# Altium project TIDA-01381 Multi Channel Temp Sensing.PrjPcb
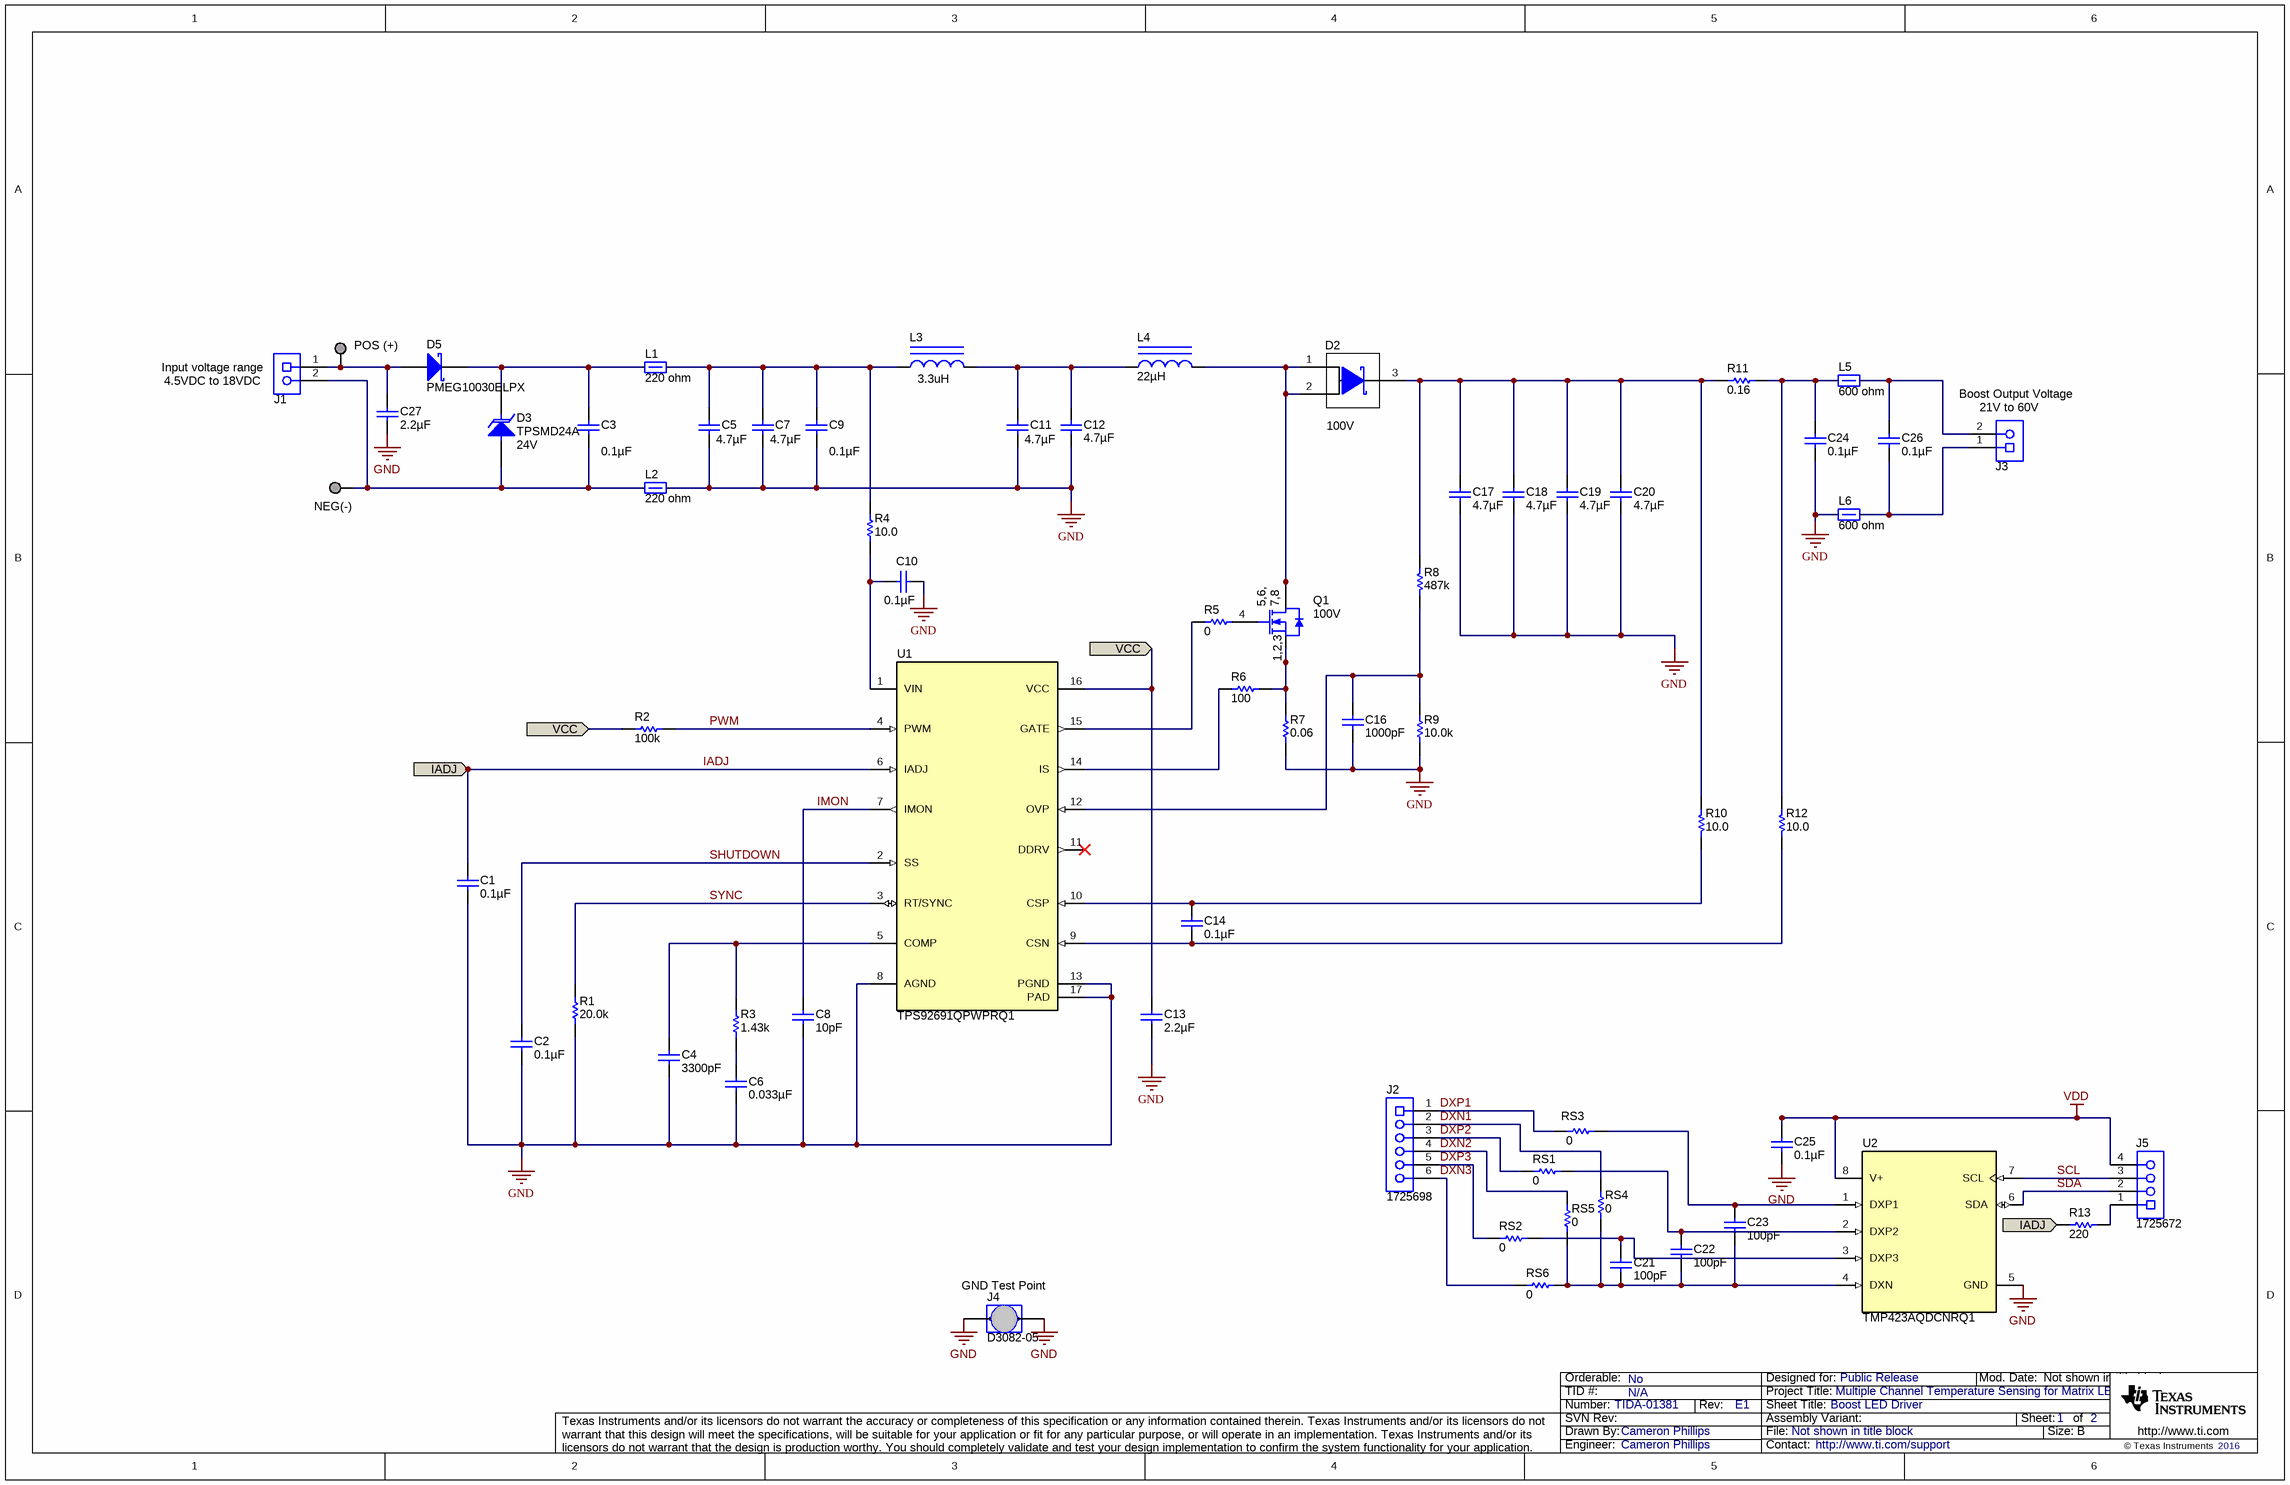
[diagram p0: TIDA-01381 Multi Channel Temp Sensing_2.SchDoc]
CopyrightYear: 2016; EVM_Orderable: No; PCB_Layout: Cameron Phillips; PCB_Rev: E1; PRJ_Customer: Public Release; PRJ_Engineer: Cameron Phillips; PRJ_Number: TIDA-01381; PRJ_Title: Multiple Channel Temperature Sensing for Matrix LED Headlight; SCH_Rev: E1; TechSupport: http://www.ti.com/support; TID: N/A
2 sheets, 84 parts. Net scope: flat (ports and power ports of the same name join across sheets).
Board file: TIDA-01381 Multi Channel Temp Sensing.PcbDoc
Sheets:
  TIDA-01381 Multi Channel Temp Sensing_2.SchDoc
  TIDA-01381 Multi Channel Temp Sensing_Hardware.SchDoc

## Sheet TIDA-01381 Multi Channel Temp Sensing_2.SchDoc: Boost LED Driver
size 431 x 279 mm; Date: Not shown in title block; ApprovedBy: Not shown in title block; CheckedBy: Not shown in title block; Author: Not shown in title block; CompanyName: Not shown in title block; DrawnBy: Cameron Phillips; Engineer: Not shown in title block; Organization: Not shown in title block; Address1: Not shown in title block; Address2: Not shown in title block; Address3: Not shown in title block; Address4: Not shown in title block; DocumentNumber: 1; Revision: Use project parameter SCH_Rev; SheetNumber: 1; SheetTotal: 2; PageSetup: Record=PageOptions¦CenterHorizontal=True¦CenterVertical=True¦PrintScale=0.61¦XCorrection=1.00¦YCorrection=1.00¦PrintKind=0¦BorderSize=5000000¦LeftOffset=0¦BottomOffset=0¦Orientation=2¦PaperLength=1000¦PaperWidth=1000¦Scale=100¦PaperSource=15¦PrintQuality=600¦MediaType=1¦DitherType=10¦PrintScaleMode=1¦PaperKind=Letter

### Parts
C1  ValueDisplayed: 0.1µF  [0603S]  (hidden comment: 06033C104JAT2A)
C2  ValueDisplayed: 0.1µF  [0603S]  (hidden comment: 06033C104JAT2A)
C3  ValueDisplayed: 0.1µF  [0805_HV]  (hidden comment: C2012X7R2A104K125AA)
C4  ValueDisplayed: 3300pF  [0603S]  (hidden comment: GRM188R71E332KA01D)
C5  ValueDisplayed: 4.7µF  [1210]  (hidden comment: C3225X7S2A475K200AE)
C6  ValueDisplayed: 0.033µF  [0805_HV]  (hidden comment: GRM216R71E333KA01D)
C7  ValueDisplayed: 4.7µF  [1210]  (hidden comment: C3225X7S2A475K200AE)
C8  ValueDisplayed: 10pF  [0603S]  (hidden comment: CGA3E2C0G1H100D080AA)
C9  ValueDisplayed: 0.1µF  [0805_HV]  (hidden comment: C2012X7R2A104K125AA)
C10  ValueDisplayed: 0.1µF  [0805_HV]  (hidden comment: C2012X7R2A104K125AA)
C11  ValueDisplayed: 4.7µF  [1210]  (hidden comment: C3225X7S2A475K200AE)
C12  ValueDisplayed: 4.7µF  [1210]  (hidden comment: C3225X7S2A475K200AE)
C13  ValueDisplayed: 2.2µF  [0805_HV]  (hidden comment: C0805C225K4RACTU)
C14  ValueDisplayed: 0.1µF  [0603S]  (hidden comment: GRM188R71H104KA93D)
C16  ValueDisplayed: 1000pF  [0603_HV]  (hidden comment: 06031C102JAT2A)
C17  ValueDisplayed: 4.7µF  [1210]  (hidden comment: C3225X7S2A475K200AE)
C18  ValueDisplayed: 4.7µF  [1210]  (hidden comment: C3225X7S2A475K200AE)
C19  ValueDisplayed: 4.7µF  [1210]  (hidden comment: C3225X7S2A475K200AE)
C20  ValueDisplayed: 4.7µF  [1210]  (hidden comment: C3225X7S2A475K200AE)
C21  ValueDisplayed: 100pF  [0603S]  (hidden comment: CGA3E2NP01H101J080AA)
C22  ValueDisplayed: 100pF  [0603S]  (hidden comment: CGA3E2NP01H101J080AA)
C23  ValueDisplayed: 100pF  [0603S]  (hidden comment: CGA3E2NP01H101J080AA)
C24  ValueDisplayed: 0.1µF  [1206_180]  (hidden comment: C3216X7R2A104K160AA)
C25  ValueDisplayed: 0.1µF  [0603S]  (hidden comment: 06033C104JAT2A)
C26  ValueDisplayed: 0.1µF  [1206_180]  (hidden comment: C3216X7R2A104K160AA)
C27  ValueDisplayed: 2.2µF  [0603]  (hidden comment: GRT188R61H225KE13D)
D2  value 100V  [PowerDI5]  (hidden comment: PDS3100Q-13)
D3  TPSMD24A  value 24V  [SMC_265]
D5  PMEG10030ELPX  [SOD-128]
J1  1727010  [PhoenixConact_1727010]  (value not drawn)
J2  1725698  [Phoenix_1725698]
J3  1727010  [PhoenixConact_1727010]  (value not drawn)
J4  D3082-05  [Harwin_D3082-05]
J5  1725672  [Phoenix_1725672]
L1  value 220 ohm  [1206]  (hidden comment: FBMH3216HM221NTV)
L2  value 220 ohm  [1206]  (hidden comment: FBMH3216HM221NTV)
L3  value 3.3uH  [CLF7045]  (hidden comment: CLF7045T-3R3N)
L4  ValueDisplayed: 22µH  [IHLP-4040DZ]  (hidden comment: IHLP4040DZER220M8A)
L5  value 600 ohm  [1206]  (hidden comment: BLM31PG601SH1L)
L6  value 600 ohm  [1206]  (hidden comment: BLM31PG601SH1L)
NEG(-)  GND  [Keystone1502-2]  (value not drawn)
POS_(+)  Suggest using a net name here  [Keystone1502-2]  (value not drawn)
Q1  value 100V  [PowerFLAT5x6_R]  (hidden comment: STL8N10LF3)
R1  ValueDisplayed: 20.0k  [0603S]  (hidden comment: CRCW060320K0FKEA)
R2  ValueDisplayed: 100k  [0603S]  (hidden comment: CRCW0603100KFKEA)
R3  ValueDisplayed: 1.43k  [0603S]  (hidden comment: CRCW06031K43FKEA)
R4  ValueDisplayed: 10.0  [1206]  (hidden comment: CRCW120610R0FKEA)
R5  ValueDisplayed: 0  [0603_HV]  (hidden comment: CRCW06030000Z0EA)
R6  ValueDisplayed: 100  [0603_HV]  (hidden comment: CRCW0603100RFKEA)
R7  ValueDisplayed: 0.06  [2010]  (hidden comment: CSRN2010FK60L0)
R8  ValueDisplayed: 487k  [0603_HV]  (hidden comment: CRCW0603487KFKEA)
R9  ValueDisplayed: 10.0k  [0603_HV]  (hidden comment: CRCW060310K0FKEA)
R10  ValueDisplayed: 10.0  [0603_HV]  (hidden comment: CRCW060310R0FKEA)
R11  ValueDisplayed: 0.16  [1210]  (hidden comment: MCR25JZHFLR160)
R12  ValueDisplayed: 10.0  [0603_HV]  (hidden comment: CRCW060310R0FKEA)
R13  ValueDisplayed: 220  [0603S]  (hidden comment: CRCW0603220RJNEA)
RS1  ValueDisplayed: 0  [0603S]  (hidden comment: ERJ-3GEY0R00V)
RS2  ValueDisplayed: 0  [0603S]  (hidden comment: ERJ-3GEY0R00V)
RS3  ValueDisplayed: 0  [0603S]  (hidden comment: ERJ-3GEY0R00V)
RS4  ValueDisplayed: 0  [0603S]  (hidden comment: ERJ-3GEY0R00V)
RS5  ValueDisplayed: 0  [0603S]  (hidden comment: ERJ-3GEY0R00V)
RS6  ValueDisplayed: 0  [0603S]  (hidden comment: ERJ-3GEY0R00V)
U1  TPS92691QPWPRQ1  [PWP0016J_N]
U2  TMP423AQDCNRQ1  [DCN0008A_N]

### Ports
IADJ, IADJ (out), VCC

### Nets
GND: C1.2 C2.2 C4.2 C5.2 C6.1 C7.2 C8.2 C9.2 C10.1 C11.2 C12.2 C13.2 C16.2 C17.1 C18.1 C19.1 C20.1 C24.2 C25.2 C27.2 J4.1 J4.2 L2.2 L6.1 R1.1 R7.1 R9.1 U1.8(AGND) U1.13(PGND) U1.17(PAD) U2.5(GND)
VDD: C25.1 J5.4 U2.8(V+)
DXN1: J2.2 RS4.1
DXN2: J2.4 RS5.1
DXN3: J2.6 RS6.2
DXP1: J2.1 RS3.1
DXP2: J2.3 RS1.1
DXP3: J2.5 RS2.1
IADJ: C1.1 R13.1 U1.6(IADJ) ; port IADJ
IMON: C8.1 U1.7(IMON)
PWM: R2.2 U1.4(PWM)
SCL: J5.3 U2.7(SCL)
SDA: J5.2 U2.6(SDA)
SHUTDOWN: C2.1 U1.2(SS)
SYNC: R1.2 U1.3(RT/SYNC)
VCC: C13.1 R2.1 U1.16(VCC) ; port VCC
NetC3_1: C3.1 D3.1(K) D5.1(K) L1.1
NetC3_2: C3.2 D3.2(A) J1.2 L2.1 NEG(-).1
NetC4_1: C4.1 R3.2 U1.5(COMP)
NetC5_1: C5.1 C7.1 C9.1 L1.2 L3.1 R4.2
NetC6_2: C6.2 R3.1
NetC10_2: C10.2 R4.1 U1.1(VIN)
NetC11_1: C11.1 C12.1 L3.2 L4.1
NetC14_1: C14.1 R10.1 U1.10(CSP)
NetC14_2: C14.2 R12.1 U1.9(CSN)
NetC16_1: C16.1 R8.1 R9.2 U1.12(OVP)
NetC17_2: C17.2 C18.2 C19.2 C20.2 D2.3(K) R8.2 R10.2 R11.1
NetC21_1: C21.1 RS2.2 U2.3(DXP3)
NetC21_2: C21.2 C22.2 C23.2 RS4.2 RS5.2 RS6.1 U2.4(DXN)
NetC22_1: C22.1 RS1.2 U2.2(DXP2)
NetC23_1: C23.1 RS3.2 U2.1(DXP1)
NetC24_1: C24.1 L5.1 R11.2 R12.2
NetC26_1: C26.1 J3.2 L5.2
NetC26_2: C26.2 J3.1 L6.2
NetC27_1: C27.1 D5.2(A) J1.1 POS_(+).1
NetD2_1: D2.1(A) D2.2(A) L4.2 Q1.5(D) Q1.6(D) Q1.7(D) Q1.8(D) Q1.9(D)
NetJ5_1: J5.1 R13.2
NetQ1_1: Q1.1(S) Q1.2(S) Q1.3(S) R6.2 R7.2
NetQ1_4: Q1.4(G) R5.2
NetR5_1: R5.1 U1.15(GATE)
NetR6_1: R6.1 U1.14(IS)

Not connected (* = marked no-connect by the designer): U1 11(DDRV)*

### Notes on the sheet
- (near J1) Input voltage range
- (near J1) 4.5VDC to 18VDC
- (near J3) 21V to 60V
- (near J3) Boost Output Voltage
- (near J4) GND Test Point

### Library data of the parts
C1 C2 C25 = 06033C104JAT2A: CAP, CERM, 0.1 µF, 25 V, +/- 5%, X7R, 0603; Manufacturer: AVX; Polarized: N; CompType: Capacitor; Value: 0.1uF; U/M: EA; Cap_F: 0.0000001; Tolerance_%: 5; ESR_ohm: 0.05; Value1: 0.05 ohm; VDC_V: 25; Value2: 25V; TaMin_C: -55; TaMax_C: 125; Cap_Case: 0603; SizeArea_mm2: 1.28; SizeAreaWB_mm2: 4.68; SizeX_mm: 1.6; SizeY_mm: 0.8; SizeZ_mm: 1; AEC Category: Q200
C3 C9 C10 = C2012X7R2A104K125AA: CAP, CERM, 0.1 µF, 100 V, +/- 10%, X7R, 0805; Manufacturer: TDK; Polarized: N; CompType: Capacitor; Value: 0.1uF; U/M: EA; Cap_F: 0.0000001; Tolerance_%: 10; ESR_ohm: 0.0158; Value1: 0.0158 ohm; VDC_V: 100; Value2: 100V; TaMin_C: -55; TaMax_C: 125; Cap_Case: 0805; AEC Category: Q200
C4 = GRM188R71E332KA01D: CAP, CERM, 3300 pF, 25 V, +/- 10%, X7R, 0603; Manufacturer: MuRata; Polarized: N; CompType: Capacitor; Value: 3300pF; U/M: EA; Cap_F: 0.0000000033; Tolerance_%: 10; Value1: Unknown; VDC_V: 25; Value2: 25V; TaMin_C: -55; TaMax_C: 125; Cap_Case: 0603; AEC Category: Q200
C5 C7 C11 C12 C17-C20 = C3225X7S2A475K200AE: CAP, CERM, 4.7 µF, 100 V, +/- 10%, X7S, 1210; Manufacturer: TDK; Polarized: N; CompType: Capacitor; Value: 4.7uF; U/M: EA; Cap_F: 0.0000047; Tolerance_%: 10; Value1: Unknown; VDC_V: 100; Value2: 100V; TaMin_C: -55; TaMax_C: 125
C6 = GRM216R71E333KA01D: CAP, CERM, 0.033 µF, 25 V, +/- 10%, X7R, 0805; Manufacturer: MuRata; Polarized: N; CompType: Capacitor; Value: 0.033uF; U/M: EA; Cap_F: 0.000000033; Tolerance_%: 10; Value1: Unknown; VDC_V: 25; Value2: 25V; TaMin_C: -55; TaMax_C: 125; Cap_Case: 0805
C8 = CGA3E2C0G1H100D080AA: CAP, CERM, 10 pF, 50 V, +/- 5%, C0G/NP0, AEC-Q200 Grade 1, 0603; Manufacturer: TDK; Polarized: N; CompType: Capacitor; Value: 10pF; U/M: EA; Cap_F: 0.00000000001; Tolerance_%: 5; Value1: Unknown; VDC_V: 50; Value2: 50V; TaMin_C: -55; TaMax_C: 125; Cap_Case: 0603; SizeArea_mm2: 1.28; SizeAreaWB_mm2: 4.68; SizeX_mm: 1.6; SizeY_mm: 0.8; SizeZ_mm: 1; AEC Category: Q200; AEC Qualified: Y
C13 = C0805C225K4RACTU: CAP, CERM, 2.2 µF, 16 V, +/- 10%, X7R, 0805; Manufacturer: Kemet; Polarized: N; CompType: Capacitor; Value: 2.2uF; U/M: EA; Cap_F: 0.0000022; Tolerance_%: 10; ESR_ohm: 0.008; Value1: 0.008 ohm; VDC_V: 16; Value2: 16V; IRMS_A: 15.55; TaMin_C: -55; TaMax_C: 125; Cap_Case: 0805; SizeArea_mm2: 2.5; SizeAreaWB_mm2: 6.75; SizeX_mm: 2; SizeY_mm: 1.25; SizeZ_mm: 1.45; AEC Category: Q200
C14 = GRM188R71H104KA93D: CAP, CERM, 0.1 µF, 50 V, +/- 10%, X7R, 0603; Manufacturer: MuRata; Polarized: N; CompType: Capacitor; Value: 0.1uF; U/M: EA; Cap_F: 0.0000001; Tolerance_%: 10; Value1: Unknown; VDC_V: 50; Value2: 50V; TaMin_C: -55; TaMax_C: 125; Cap_Case: 0603; SizeArea_mm2: 1.28; SizeAreaWB_mm2: 4.68; SizeX_mm: 1.6; SizeY_mm: 0.8; SizeZ_mm: 1; AEC Category: Q200
C16 = 06031C102JAT2A: CAP, CERM, 1000 pF, 100 V, +/- 5%, X7R, 0603; Manufacturer: AVX; Polarized: N; CompType: Capacitor; Value: 1000pF; U/M: EA; Cap_F: 0.000000001; Tolerance_%: 5; ESR_ohm: 0.276; Value1: 0.276 ohm; VDC_V: 100; Value2: 100V; TaMin_C: -55; TaMax_C: 125; Cap_Case: 0603; SizeArea_mm2: 1.28; SizeAreaWB_mm2: 4.68; SizeX_mm: 1.6; SizeY_mm: 0.8; SizeZ_mm: 1; AEC Category: Q200
C21-C23 = CGA3E2NP01H101J080AA: CAP, CERM, 100 pF, 50 V, +/- 5%, C0G/NP0, AEC-Q200 Grade 0, 0603; Manufacturer: TDK; Polarized: N; CompType: Capacitor; Value: 100pF; U/M: EA; Cap_F: 0.0000000001; Tolerance_%: 5; Value1: Unknown; VDC_V: 50; Value2: 50V; TaMin_C: -55; TaMax_C: 150; Cap_Case: 0603; SizeArea_mm2: 1.28; SizeAreaWB_mm2: 4.68; SizeX_mm: 1.6; SizeY_mm: 0.8; SizeZ_mm: 1; AEC Category: Q200; AEC Qualified: Y; AEC Grade: 0
C24 C26 = C3216X7R2A104K160AA: CAP, CERM, 0.1 µF, 100 V, +/- 10%, X7R, 1206; Manufacturer: TDK; Polarized: N; CompType: Capacitor; Value: 0.1uF; U/M: EA; Cap_F: 0.0000001; Tolerance_%: 10; ESR_ohm: 0.030343; Value1: 0.030343 ohm; VDC_V: 100; Value2: 100V; IRMS_A: 1.33802; TaMin_C: -55; TaMax_C: 125; SizeArea_mm2: 5.12; SizeAreaWB_mm2: 10.92; SizeX_mm: 3.2; SizeY_mm: 1.6; SizeZ_mm: 1.8; AEC Category: Q200
C27 = GRT188R61H225KE13D: CAP, CERM, 2.2 µF, 50 V, +/- 10%, X5R, AEC-Q200 Grade 3, 0603; Manufacturer: MuRata; Polarized: N; CompType: Capacitor; Value: 2.2uF; U/M: EA; Cap_F: 0.0000022; Tolerance_%: 10; Value1: Unknown; VDC_V: 50; Value2: 50V; TaMin_C: -55; TaMax_C: 85; SizeArea_mm2: 1.28; SizeAreaWB_mm2: 4.68; SizeX_mm: 1.6; SizeY_mm: 0.8; SizeZ_mm: 1; AEC Category: Q200; AEC Qualified: Y; AEC Grade: 3
D2 = PDS3100Q-13: Diode, Schottky, 100 V, 3 A, AEC-Q101, PowerDI5; Manufacturer: Diodes Inc.; U/M: EA; Vf_V: 0.76; Value1: 3A; Value2: 0.76V; Io_A: 3; Vr_V: 100; TJmax_C: 150; AEC Category: Q101; AEC Qualified: Y
D3 = TPSMD26A: Diode, TVS, Uni, 24 V, 38.9 Vc, AEC-Q101, SMC; Manufacturer: Littelfuse; U/M: EA; Power_W: 6.5; Vr_V: 24; Value1: 6.5W; RJA_CperW: 75; SizeAreaWB_mm2: 78.5757; SizeArea_mm2: 46.8857; SizeX_mm: 7.94; SizeY_mm: 5.905; SizeZ_mm: 2.62; AEC Category: Q101; AEC Qualified: Y
D5 = PMEG10030ELPX: Diode, Schottky, 100 V, 3 A, AEC-Q101, SOD-128; Manufacturer: NXP Semiconductor; U/M: EA; Vf_V: 0.77; Value: 100V; Value1: 3A; Value2: 0.77V; Io_A: 3; Vr_V: 100; TJmax_C: 175; SizeAreaWB_mm2: 19.6; SizeArea_mm2: 11.5; SizeX_mm: 4.6; SizeY_mm: 2.5; SizeZ_mm: 1.1; AEC Category: Q101; AEC Qualified: Y
J1 J3 = 1727010: Conn Term Block, 2POS, 3.81mm, TH; Manufacturer: Phoenix Contact; SymbolCreator: a0412235; CompType: Terminal Block
J2 = 1725698: Terminal Block, 6x1, 2.54mm, TH; Manufacturer: Phoenix Contact; SymbolCreator: a0411947; Pitch_mm: 2.54; Row_Count: 1; Current_A: 6; Voltage_V: 160; Cert_CSA: Y
J4 = D3082-05: 1mm Uninsulated Shorting Plug, 10.16mm spacing, TH; Manufacturer: Harwin; SymbolCreator: a0799628; CompType: Jumper Wire
J5 = 1725672: Terminal Block, 4x1, 2.54 mm, Green, TH; Manufacturer: Phoenix Contact; SymbolCreator: a0411947; Pitch_mm: 2.54; Gender: Female; Row_Count: 1; Current_A: 6; Voltage_V: 125; Cert_CSA: Y
L1 L2 = FBMH3216HM221NTV: Ferrite Bead, 220 ohm @ 100 MHz, 4 A, 1206; Manufacturer: Taiyo Yuden; Imax_A: 4; DCR_ohm: 0.02; Value1: 0.02 ohm; Value2: 4A; SizeAreaWB_mm2: 10.92; SizeArea_mm2: 5.12; SizeX_mm: 3.2; SizeY_mm: 1.6; SizeZ_mm: 1.35; ZTyp@100MHz_Ohm: 220
L3 = CLF7045T-3R3N: Inductor, Shielded, Ferrite, 3.3 µH, 5 A, 0.0213 ohm, SMD; Manufacturer: TDK; Ind_H: 3.3E-6; ValueDisplayed: 3.3µH; Imax_A: 5; Irms: 4.1A @ 30C rise; Isat: 5A @ 10% inductance drop; DCR_ohm: 0.0213; Value2: 5A
L4 = IHLP4040DZER220M8A: Inductor, Shielded Drum Core, Powdered Iron, 22 µH, 4.1 A, 0.0705 ohm, AEC-Q200 Grade 0, SMD; Manufacturer: Vishay-Dale; Value: 22uH; Ind_H: 22.0E-6; Imax_A: 4.1; Irms: 4.1A @ 40C rise; Isat: 6.4A @ 20% inductance drop; DCR_ohm: 0.0705; Value2: 4.1A; AEC Category: Q200; AEC Qualified: Y; AEC Grade: 0
L5 L6 = BLM31PG601SH1L: Ferrite Bead, 600 ohm @ 100 MHz, 1.5 A, 1206; Manufacturer: MuRata; Imax_A: 1.5; DCR_ohm: 0.08; Value1: 0.08 ohm; Value2: 1.5A; SizeAreaWB_mm2: 10.92; SizeArea_mm2: 5.12; SizeX_mm: 3.2; SizeY_mm: 1.6; SizeZ_mm: 1.35; ZTyp@100MHz_Ohm: 600
NEG(-) POS_(+) = 1502-2: Terminal, Turret, TH, Double; Manufacturer: Keystone; CompType: Turret Terminal; U/M: EA
Q1 = STL8N10LF3: MOSFET, N-CH, 100 V, 20 A, AEC-Q101, 8-PowerVDFN; Manufacturer: STMicroelectronics; Alternate Manufacturer: None; U/M: EA; ChType: N; VdsMax_V: 100; Value1: ? ohm; Value2: 20.5 nC; QgTyp_nC: 20.5; Vgs_V: 20; AEC Category: Q101; AEC Qualified: Y
R1 = CRCW060320K0FKEA: RES, 20.0 k, 1%, 0.1 W, 0603; Manufacturer: Vishay-Dale; CompType: Resistor; Value: 20.0k; Res_ohm: 20000; Value_Code: 20k0; Tolerance_%: 1; Power_W: 0.1; Value2: 0.1W; VDC_V: 75; TempCo: 100 ppm/C; EIA_Code: E96; U/M: EA
R2 = CRCW0603100KFKEA: RES, 100 k, 1%, 0.1 W, 0603; Manufacturer: Vishay-Dale; CompType: Resistor; Value: 100k; Res_ohm: 100000; Tolerance_%: 1; Power_W: 0.1; Value2: 0.1W; VDC_V: 75; TempCo: 100 ppm/C; EIA_Code: E96; U/M: EA
R3 = CRCW06031K43FKEA: RES, 1.43 k, 1%, 0.1 W, 0603; Manufacturer: Vishay-Dale; CompType: Resistor; Value: 1.43k; Res_ohm: 1430; Value_Code: 1k43; Tolerance_%: 1; Power_W: 0.1; Value2: 0.1W; VDC_V: 75; TempCo: 100 ppm/C; EIA_Code: E96; U/M: EA; AEC Category: Q200
R4 = CRCW120610R0FKEA: RES, 10.0, 1%, 0.25 W, 1206; Manufacturer: Vishay-Dale; CompType: Resistor; Value: 10.0; Res_ohm: 10; Value_Code: 10R0; Tolerance_%: 1; Power_W: 0.25; Value2: 0.25W; VDC_V: 200; TempCo: 100 ppm/C; EIA_Code: E96; U/M: EA
R5 = CRCW06030000Z0EA: RES, 0, 5%, 0.1 W, 0603; Manufacturer: Vishay-Dale; CompType: Resistor; Value: 0; Value_Code: 0000; Tolerance_%: 5; Power_W: 0.1; Value2: 0.1W; VDC_V: 75; TempCo: 200 ppm/C; EIA_Code: E24; U/M: EA; AEC Category: Q200
R6 = CRCW0603100RFKEA: RES, 100, 1%, 0.1 W, 0603; Manufacturer: Vishay-Dale; CompType: Resistor; Value: 100; Value_Code: 100R; Tolerance_%: 1; Power_W: 0.1; Value2: 0.1W; VDC_V: 75; TempCo: 100 ppm/C; EIA_Code: E96; U/M: EA; AEC Category: Q200
R7 = CSRN2010FK60L0: RES, 0.06, 1%, 1 W, 2010; Manufacturer: Stackpole Electronics Inc; CompType: Resistor; Value: 0.06; Value_Code: R060; Tolerance_%: 1; Value2: 1W; TempCo: 250 ppm/C; U/M: EA
R8 = CRCW0603487KFKEA: RES, 487 k, 1%, 0.1 W, 0603; Manufacturer: Vishay-Dale; CompType: Resistor; Value: 487k; Res_ohm: 487000; Tolerance_%: 1; Power_W: 0.1; Value2: 0.1W; VDC_V: 75; TempCo: 100 ppm/C; EIA_Code: E96; U/M: EA
R9 = CRCW060310K0FKEA: RES, 10.0 k, 1%, 0.1 W, 0603; Manufacturer: Vishay-Dale; CompType: Resistor; Value: 10.0k; Res_ohm: 10000; Value_Code: 10k0; Tolerance_%: 1; Power_W: 0.1; Value2: 0.1W; VDC_V: 75; TempCo: 100 ppm/C; EIA_Code: E96; U/M: EA
R10 R12 = CRCW060310R0FKEA: RES, 10.0, 1%, 0.1 W, 0603; Manufacturer: Vishay-Dale; CompType: Resistor; Value: 10.0; Res_ohm: 10; Value_Code: 10R0; Tolerance_%: 1; Power_W: 0.1; Value2: 0.1W; VDC_V: 75; TempCo: 100 ppm/C; EIA_Code: E96; U/M: EA
R11 = MCR25JZHFLR160: RES, 0.16, 1%, 0.5 W, 1210; Manufacturer: Rohm; CompType: Resistor; Value: 0.16; Value_Code: R160; Tolerance_%: 1; Power_W: 0.5; Value2: 0.5W; VDC_V: 0; TempCo: 200 ppm/C; EIA_Code: E96; U/M: EA; AEC Category: Q200
R13 = CRCW0603220RJNEA: RES, 220, 5%, 0.1 W, 0603; Manufacturer: Vishay-Dale; CompType: Resistor; Value: 220; Value_Code: 220R; Tolerance_%: 5; Power_W: 0.1; Value2: 0.1W; VDC_V: 75; TempCo: 200 ppm/C; SizeArea_mm2: 1.28; SizeX_mm: 1.6; SizeY_mm: 0.8; SizeZ_mm: 1; EIA_Code: E24; U/M: EA; AEC Category: Q200
RS1-RS6 = ERJ-3GEY0R00V: RES, 0, 5%, 0.1 W, 0603; Manufacturer: Panasonic; CompType: Resistor; Value: 0; Value_Code: 0000; Tolerance_%: 5; Power_W: 0.1; Value2: 0.1W; VDC_V: 50; TempCo: 600 ppm/C; SizeArea_mm2: 1.28; SizeX_mm: 1.6; SizeY_mm: 0.8; SizeZ_mm: 1; EIA_Code: E24; U/M: EA; AEC Category: Q200
U1 = TPS92691QPWPRQ1: Multi-Topology LED Driver with Rail-to-Rail Current Sense Amplifier, PWP0016J; Alternate PartNumber: TPS92691QPWPTQ1; Manufacturer: Texas Instruments; SymbolCreator: Altium; SizeArea_mm2: 32; SizeAreaWB_mm2: 58.8; SizeX_mm: 6.4; SizeY_mm: 5; SizeZ_mm: 1.2; CompType: IC; U/M: EA
U2 = TMP423BIDCNR: +/- 1 C Remote and Local TEMPERATURE SENSOR, DCN0008A (SOT-8); Alternate PartNumber: TMP423AIDCNT; Manufacturer: Texas Instruments; SymbolCreator: a0411947; SizeArea_mm2: 8.41; SizeAreaWB_mm2: 15.21; SizeX_mm: 2.9; SizeZ_mm: 1.1; CompType: IC; U/M: EA

## Sheet TIDA-01381 Multi Channel Temp Sensing_Hardware.SchDoc: Hardware
size 431 x 279 mm; Date: Not shown in title block; ApprovedBy: Not shown in title block; CheckedBy: Not shown in title block; Author: Not shown in title block; CompanyName: Not shown in title block; Engineer: Not shown in title block; Organization: Not shown in title block; Address1: Not shown in title block; Address2: Not shown in title block; Address3: Not shown in title block; Address4: Not shown in title block; DocumentNumber: 2; Revision: Use project parameter SCH_Rev; SheetNumber: 2; SheetTotal: 2; PageSetup: Record=PageOptions¦CenterHorizontal=True¦CenterVertical=True¦PrintScale=1.00¦XCorrection=1.00¦YCorrection=1.00¦PrintKind=0¦BorderSize=5000000¦LeftOffset=0¦BottomOffset=0¦Orientation=2¦PaperLength=1000¦PaperWidth=1000¦Scale=100¦PaperSource=15¦PrintQuality=600¦MediaType=1¦DitherType=10¦PaperKind=Letter¦PrintScaleMode=1
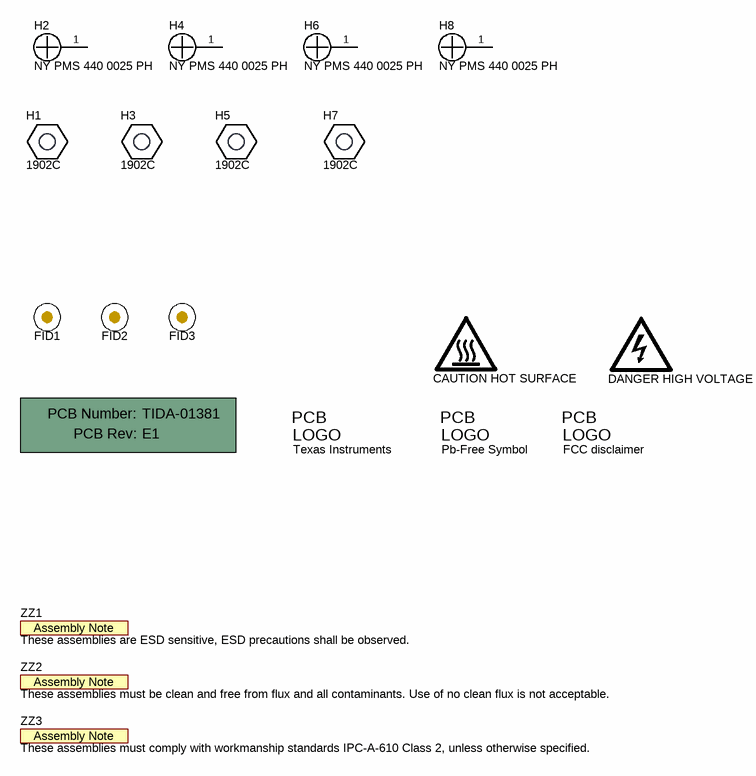
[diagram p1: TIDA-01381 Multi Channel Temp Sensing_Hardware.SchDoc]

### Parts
!PCB1  Printed Circuit Board  (value not drawn)  (mechanical)
FID1  Fiducial  [Fiducial10-20]  (value not drawn)
FID2  Fiducial  [Fiducial10-20]  (value not drawn)
FID3  Fiducial  [Fiducial10-20]  (value not drawn)
H1  1902C  [Keystone_1902C]
H2  NY PMS 440 0025 PH  [NY PMS 440 0025 PH]
H3  1902C  [Keystone_1902C]
H4  NY PMS 440 0025 PH  [NY PMS 440 0025 PH]
H5  1902C  [Keystone_1902C]
H6  NY PMS 440 0025 PH  [NY PMS 440 0025 PH]
H7  1902C  [Keystone_1902C]
H8  NY PMS 440 0025 PH  [NY PMS 440 0025 PH]
Logo1  Texas Instruments  [TI_Stacked_Overlay_Small]  (no BOM)
LOGO2  CAUTION HOT SURFACE  [IEC_HotSurface_Small]  (no BOM)
Logo3  Pb-Free Symbol  [Pb-Free_Overlay_Small]  (no BOM)
Logo4  FCC disclaimer  [FCC_disclaimer]  (no BOM)
LOGO5  DANGER HIGH VOLTAGE  [IEC_HighVoltage_Small]  (no BOM)
ZZ1  These assemblies are ESD sensitive, ESD precautions shall be observed.  [AssemblyNote]  (no BOM)
ZZ2  These assemblies must be clean and free from flux and all contaminants. Use of no clean flux is not acceptable.  [AssemblyNote]  (no BOM)
ZZ3  These assemblies must comply with workmanship standards IPC-A-610 Class 2, unless otherwise specified.  [AssemblyNote]  (no BOM)

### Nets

Not connected (* = marked no-connect by the designer): H2 1; H4 1; H6 1; H8 1

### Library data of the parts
!PCB1 = PCB: Manufacturer: Any; PartNumber: TIDA-01381; SymbolCreator: a0412235
FID1-FID3 = Fiducial: Fiducial mark.  There is nothing to buy or mount.; SymbolCreator: codlsc
H1 H3 H5 H7 = 1902C: Standoff, Hex, 0.5"L #4-40 Nylon; Manufacturer: Keystone; SymbolCreator: a0412235; CompType: Hardware
H2 H4 H6 H8 = NY PMS 440 0025 PH: Machine Screw, Round, #4-40 x 1/4, Nylon, Philips panhead; Manufacturer: B&F Fastener Supply; CompType: Hardware; SymbolCreator: codlsc; U/M: EA
Logo1 = TI_Logo: Texas Instrument Corporate Signature; SymbolCreator: codlsc
LOGO2 = IEC_HotSurface: IEC 61010-1 Hot Surface Warning; SymbolCreator: a0412235
Logo3 = Pb-Free: SymbolCreator: a0412235
Logo4 = FCC_disclaimer: SymbolCreator: codlsc
LOGO5 = IEC_HighVoltage: IEC 61010-1 High Voltage Warning; SymbolCreator: a0412235
ZZ1-ZZ3 = AssemblyNote: SymbolCreator: codlsc

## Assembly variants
001: not fitted C15 C16 FID1 FID2 FID3 R3 R5 R18 TP3 TP4 TP5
